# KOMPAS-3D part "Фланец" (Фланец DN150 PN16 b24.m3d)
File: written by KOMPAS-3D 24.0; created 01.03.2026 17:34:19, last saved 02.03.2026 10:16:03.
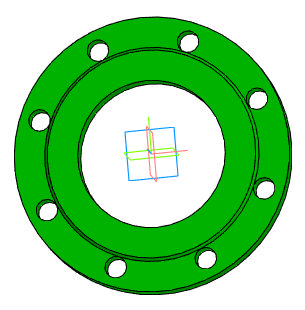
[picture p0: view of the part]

Document properties: Автор: R2D2; Полное имя файла: E:\Работа\Зайцев\GVWR2626M-2W-F-S Задвижка клиновая с выдвижным штоком DN.ru Ду50-300 Ру16\DN150\исходные материалы\Фланец DN150 PN16 b24.m3d

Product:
- Part/product: Фланец
    Масса: 7.180576
    additional columns: Типовые

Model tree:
1. Эскиз:2
2. Элемент вращения:1
     Угол 1 = 360
3. Эскиз:3  (with: Грань.Элемент вращения:1)
4. Элемент выдавливания:2
     Расстояние 2 = 21
5. Массив по концентрической сетке:1  (with: Элемент выдавливания:2, Эскиз:3, Грань.Элемент вращения:1)  (8 pattern instances)
     Шаг 2 = 360
6. Эскиз:4  (with: Грань.Элемент вращения:1)
7. Элемент выдавливания:3
     Расстояние 2 = 4

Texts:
  Линейный размер с обрывом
